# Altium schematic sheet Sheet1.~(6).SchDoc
size A4
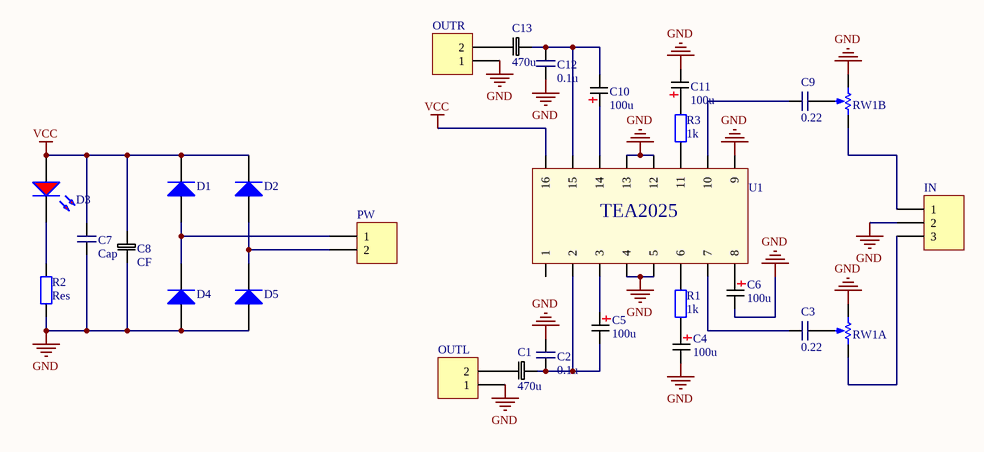
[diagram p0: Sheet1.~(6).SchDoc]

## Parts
C1  470u  [CF0.1]
C2  0.1u  [RAD0.1]
C3  0.22  [RAD0.1]
C4  100u  [CF0.1]
C5  100u  [CF0.1]
C6  100u  [CF0.1]
C7  Cap  [RAD0.1]
C8  CF  [CF0.1]
C9  0.22  [RAD0.1]
C10  100u  [CF0.1]
C11  100u  [CF0.1]
C12  0.1u  [RAD0.1]
C13  470u  [CF0.1]
D1  Diode 1N4007  [DIO10.46-5.3x2.8]  (value not drawn)
D2  Diode 1N4007  [DIO10.46-5.3x2.8]  (value not drawn)
D3  LED0  [LED]  (value not drawn)
D4  Diode 1N4007  [DIO10.46-5.3x2.8]  (value not drawn)
D5  Diode 1N4007  [DIO10.46-5.3x2.8]  (value not drawn)
IN  (no value)  [HDR1X3]
OUTL  Header 2  [HDR1X2]  (value not drawn)
OUTR  Header 2  [HDR1X2]  (value not drawn)
PW  Header 2  [HDR1X2]  (value not drawn)
R1  1k  [AXIAL-0.3]
R2  Res  [AXIAL-0.3]
R3  1k  [AXIAL-0.3]
RW1  RW  [RW]  (value not drawn)  (parts A,B of 2)
U1  TEA2025  [DIP16]  (value not drawn)

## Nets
GND: C2.1 C4.2 C6.2 C7.1 C8.2 C11.2 C12.2 D4.1(A) D5.1(A) IN.2 OUTL.1 OUTR.1 R2.1 RW1.1(TOP) RW1.4(TOP) U1.4 U1.5 U1.9 U1.12 U1.13
VCC: C7.2 C8.1 D1.2(K) D2.2(K) D3.1(A) U1.16
NetC1_1: C1.1 C2.2 C5.2 U1.2
NetC1_2: C1.2 OUTL.2
NetC3_1: C3.1 RW1.2(TAP)
NetC3_2: C3.2 U1.7
NetC4_1: C4.1 R1.2
NetC5_1: C5.1 U1.3
NetC6_1: C6.1 U1.8
NetC9_1: C9.1 RW1.5(TAP)
NetC9_2: C9.2 U1.10
NetC10_1: C10.1 U1.14
NetC10_2: C10.2 C12.1 C13.1 U1.15
NetC11_1: C11.1 R3.1
NetC13_2: C13.2 OUTR.2
NetD1_1: D1.1(A) D4.2(K) PW.1
NetD2_1: D2.1(A) D5.2(K) PW.2
NetD3_2: D3.2(K) R2.2
NetIN_1: IN.1 RW1.6(BOT)
NetIN_3: IN.3 RW1.3(BOT)
NetR1_1: R1.1 U1.6
NetR3_2: R3.2 U1.11

Not connected (* = marked no-connect by the designer): U1 1

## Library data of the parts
C1 C13 = CF
C2 C3 C9 C12 = Cap
C4-C6 C10 C11 = Cap Pol
D1 D2 D4 D5 = Diode 1N4007: 1 Amp General Purpose Rectifier
IN = Header 3H: Header, 3-Pin, Right Angle
OUTL OUTR PW = Header 2: Header, 2-Pin
R1 R3 = Res: Resistor
R2 = Res: Resistor; Value: 1K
